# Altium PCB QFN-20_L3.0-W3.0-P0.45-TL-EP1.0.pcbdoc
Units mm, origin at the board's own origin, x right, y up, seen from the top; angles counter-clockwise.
Board outline 16.65 x 16.3 mm, 2 copper layers (Top Layer, Bottom Layer), stack 0 mm thick; 1 components, 0 nets, 21 pads, 0 vias.
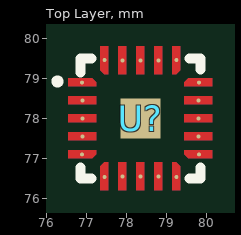
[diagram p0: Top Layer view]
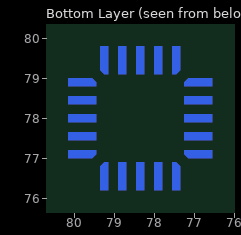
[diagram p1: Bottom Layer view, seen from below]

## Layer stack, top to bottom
Top Layer: signal copper (thickness not stored)
Bottom Layer: signal copper (thickness not stored)

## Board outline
86.5,69.85 69.85,69.85 69.85,86.15 86.5,86.15

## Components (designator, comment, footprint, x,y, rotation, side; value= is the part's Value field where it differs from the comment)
U? "" QFN-20_L3.0-W3.0-P0.45-TL-EP1.0 78.35,78 r0 top

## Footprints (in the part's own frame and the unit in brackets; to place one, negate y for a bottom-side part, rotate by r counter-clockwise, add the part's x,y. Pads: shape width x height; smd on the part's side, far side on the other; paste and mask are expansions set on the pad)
QFN-20_L3.0-W3.0-P0.45-TL-EP1.0 [mm]
  round 0.098 smd: 1(-1.462,0.898) 5(-1.462,-0.897) 6(-0.898,-1.462) 11(1.462,-0.897) 16(0.897,1.462) 20(-0.898,1.462)
  round 0.1 smd: 2(-1.45,0.45) 3(-1.45,0) 4(-1.45,-0.45) 7(-0.45,-1.45) 8(0,-1.45) 9(0.45,-1.45) 12(1.45,-0.45) 13(1.45,0) 14(1.45,0.45) 17(0.45,1.45) 18(0,1.45) 19(-0.45,1.45)
  round 0.097 smd: 10(0.897,-1.462) 15(1.462,0.898)
  rect 1x1 smd paste-100 mask+0.05: 21(0,0)
  Top Layer region: -0.8,1.1 -0.8,1.8 -1,1.8 -1,1.25 -1,1.2 -0.9,1.1
  Top Layer region: -0.55,1.2 -0.55,1.1 -0.35,1.1 -0.35,1.8 -0.55,1.8
  Top Layer region: -0.1,-1.7 -0.1,-1.8 0.1,-1.8 0.1,-1.1 -0.1,-1.1
  Top Layer region: -0.55,-1.7 -0.55,-1.8 -0.35,-1.8 -0.35,-1.1 -0.55,-1.1
  Top Layer region: -1.1,-0.8 -1.8,-0.8 -1.8,-1 -1.25,-1 -1.2,-1 -1.1,-0.9
  Top Layer region: -1.2,-0.55 -1.1,-0.55 -1.1,-0.35 -1.8,-0.35 -1.8,-0.55
  Top Layer region: -1.2,-0.1 -1.1,-0.1 -1.1,0.1 -1.8,0.1 -1.8,-0.1
  Top Layer region: -1.2,0.35 -1.1,0.35 -1.1,0.55 -1.8,0.55 -1.8,0.35
  Top Layer region: 1.2,-0.55 1.1,-0.55 1.1,-0.35 1.8,-0.35 1.8,-0.55
  Top Layer region: 1.2,-0.1 1.1,-0.1 1.1,0.1 1.8,0.1 1.8,-0.1
  Top Layer region: 1.2,0.35 1.1,0.35 1.1,0.55 1.8,0.55 1.8,0.35
  Top Layer region: 0.55,1.2 0.55,1.1 0.35,1.1 0.35,1.8 0.55,1.8
  Top Layer region: 0.1,1.2 0.1,1.1 -0.1,1.1 -0.1,1.8 0.1,1.8
  Top Layer region: 1.1,-0.8 1.8,-0.8 1.8,-1 1.25,-1 1.2,-1 1.1,-0.9
  Top Layer region: 0.8,-1.1 0.8,-1.8 1,-1.8 1,-1.25 1,-1.2 0.9,-1.1
  Top Layer region: 0.8,1.1 0.8,1.8 1,1.8 1,1.25 1,1.2 0.9,1.1
  Top Layer region: 1.1,0.8 1.8,0.8 1.8,1 1.25,1 1.2,1 1.1,0.9
  Top Layer region: -1.1,0.8 -1.8,0.8 -1.8,1 -1.25,1 -1.2,1 -1.1,0.9
  Top Layer region: -0.8,-1.1 -0.8,-1.8 -1,-1.8 -1,-1.25 -1,-1.2 -0.9,-1.1
  Top Layer region: 0.55,-1.7 0.55,-1.8 0.35,-1.8 0.35,-1.1 0.55,-1.1
  Bottom Layer region: -0.8,1.1 -0.8,1.8 -1,1.8 -1,1.25 -1,1.2 -0.9,1.1
  Bottom Layer region: -0.55,1.2 -0.55,1.1 -0.35,1.1 -0.35,1.8 -0.55,1.8
  Bottom Layer region: -0.1,-1.7 -0.1,-1.8 0.1,-1.8 0.1,-1.1 -0.1,-1.1
  Bottom Layer region: -0.55,-1.7 -0.55,-1.8 -0.35,-1.8 -0.35,-1.1 -0.55,-1.1
  Bottom Layer region: -1.1,-0.8 -1.8,-0.8 -1.8,-1 -1.25,-1 -1.2,-1 -1.1,-0.9
  Bottom Layer region: -1.2,-0.55 -1.1,-0.55 -1.1,-0.35 -1.8,-0.35 -1.8,-0.55
  Bottom Layer region: -1.2,-0.1 -1.1,-0.1 -1.1,0.1 -1.8,0.1 -1.8,-0.1
  Bottom Layer region: -1.2,0.35 -1.1,0.35 -1.1,0.55 -1.8,0.55 -1.8,0.35
  Bottom Layer region: 1.2,-0.55 1.1,-0.55 1.1,-0.35 1.8,-0.35 1.8,-0.55
  Bottom Layer region: 1.2,-0.1 1.1,-0.1 1.1,0.1 1.8,0.1 1.8,-0.1
  Bottom Layer region: 1.2,0.35 1.1,0.35 1.1,0.55 1.8,0.55 1.8,0.35
  Bottom Layer region: 0.55,1.2 0.55,1.1 0.35,1.1 0.35,1.8 0.55,1.8
  Bottom Layer region: 0.1,1.2 0.1,1.1 -0.1,1.1 -0.1,1.8 0.1,1.8
  Bottom Layer region: 1.1,-0.8 1.8,-0.8 1.8,-1 1.25,-1 1.2,-1 1.1,-0.9
  Bottom Layer region: 0.8,-1.1 0.8,-1.8 1,-1.8 1,-1.25 1,-1.2 0.9,-1.1
  Bottom Layer region: 0.8,1.1 0.8,1.8 1,1.8 1,1.25 1,1.2 0.9,1.1
  Bottom Layer region: 1.1,0.8 1.8,0.8 1.8,1 1.25,1 1.2,1 1.1,0.9
  Bottom Layer region: -1.1,0.8 -1.8,0.8 -1.8,1 -1.25,1 -1.2,1 -1.1,0.9
  Bottom Layer region: -0.8,-1.1 -0.8,-1.8 -1,-1.8 -1,-1.25 -1,-1.2 -0.9,-1.1
  Bottom Layer region: 0.55,-1.7 0.55,-1.8 0.35,-1.8 0.35,-1.1 0.55,-1.1
  Multi-Layer region: -0.8,1.1 -0.8,1.8 -1,1.8 -1,1.25 -1,1.2 -0.9,1.1
  Multi-Layer region: -0.55,1.2 -0.55,1.1 -0.35,1.1 -0.35,1.8 -0.55,1.8
  Multi-Layer region: -0.1,-1.7 -0.1,-1.8 0.1,-1.8 0.1,-1.1 -0.1,-1.1
  Multi-Layer region: -0.55,-1.7 -0.55,-1.8 -0.35,-1.8 -0.35,-1.1 -0.55,-1.1
  Multi-Layer region: -1.1,-0.8 -1.8,-0.8 -1.8,-1 -1.25,-1 -1.2,-1 -1.1,-0.9
  Multi-Layer region: -1.2,-0.55 -1.1,-0.55 -1.1,-0.35 -1.8,-0.35 -1.8,-0.55
  Multi-Layer region: -1.2,-0.1 -1.1,-0.1 -1.1,0.1 -1.8,0.1 -1.8,-0.1
  Multi-Layer region: -1.2,0.35 -1.1,0.35 -1.1,0.55 -1.8,0.55 -1.8,0.35
  Multi-Layer region: 1.2,-0.55 1.1,-0.55 1.1,-0.35 1.8,-0.35 1.8,-0.55
  Multi-Layer region: 1.2,-0.1 1.1,-0.1 1.1,0.1 1.8,0.1 1.8,-0.1
  Multi-Layer region: 1.2,0.35 1.1,0.35 1.1,0.55 1.8,0.55 1.8,0.35
  Multi-Layer region: 0.55,1.2 0.55,1.1 0.35,1.1 0.35,1.8 0.55,1.8
  Multi-Layer region: 0.1,1.2 0.1,1.1 -0.1,1.1 -0.1,1.8 0.1,1.8
  Multi-Layer region: 1.1,-0.8 1.8,-0.8 1.8,-1 1.25,-1 1.2,-1 1.1,-0.9
  Multi-Layer region: 0.8,-1.1 0.8,-1.8 1,-1.8 1,-1.25 1,-1.2 0.9,-1.1
  Multi-Layer region: 0.8,1.1 0.8,1.8 1,1.8 1,1.25 1,1.2 0.9,1.1
  Multi-Layer region: 1.1,0.8 1.8,0.8 1.8,1 1.25,1 1.2,1 1.1,0.9
  Multi-Layer region: -1.1,0.8 -1.8,0.8 -1.8,1 -1.25,1 -1.2,1 -1.1,0.9
  Multi-Layer region: -0.8,-1.1 -0.8,-1.8 -1,-1.8 -1,-1.25 -1,-1.2 -0.9,-1.1
  Multi-Layer region: 0.55,-1.7 0.55,-1.8 0.35,-1.8 0.35,-1.1 0.55,-1.1
  silkscreen extent -2.15,-1.5 1.5,1.5

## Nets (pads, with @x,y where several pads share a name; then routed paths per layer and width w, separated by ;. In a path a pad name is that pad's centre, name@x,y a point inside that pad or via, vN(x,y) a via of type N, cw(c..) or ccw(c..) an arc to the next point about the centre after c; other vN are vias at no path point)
pads on no net: U?.1 U?.2 U?.3 U?.4 U?.5 U?.6 U?.7 U?.8 U?.9 U?.10 U?.11 U?.12 U?.13 U?.14 U?.15 U?.16 U?.17 U?.18 U?.19 U?.20 U?.21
